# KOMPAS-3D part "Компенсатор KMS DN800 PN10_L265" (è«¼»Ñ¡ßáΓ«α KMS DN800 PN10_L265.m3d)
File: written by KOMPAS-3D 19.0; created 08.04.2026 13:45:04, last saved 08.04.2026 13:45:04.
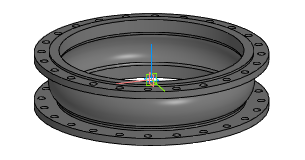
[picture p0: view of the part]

Document properties: Автор: Энергия; Полное имя файла: Z:\3.Личные\kachalov\3d для проектировщиков\7.1 Компенсатор\stp_Компенсатор KSM\Компенсатор KMS DN800 PN10_L265.m3d

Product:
- Part/product: Компенсатор KMS DN800 PN10_L265

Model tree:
1. Операция без истории:1  (labels: Компенсатор KMS DN800 PN10_L265)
